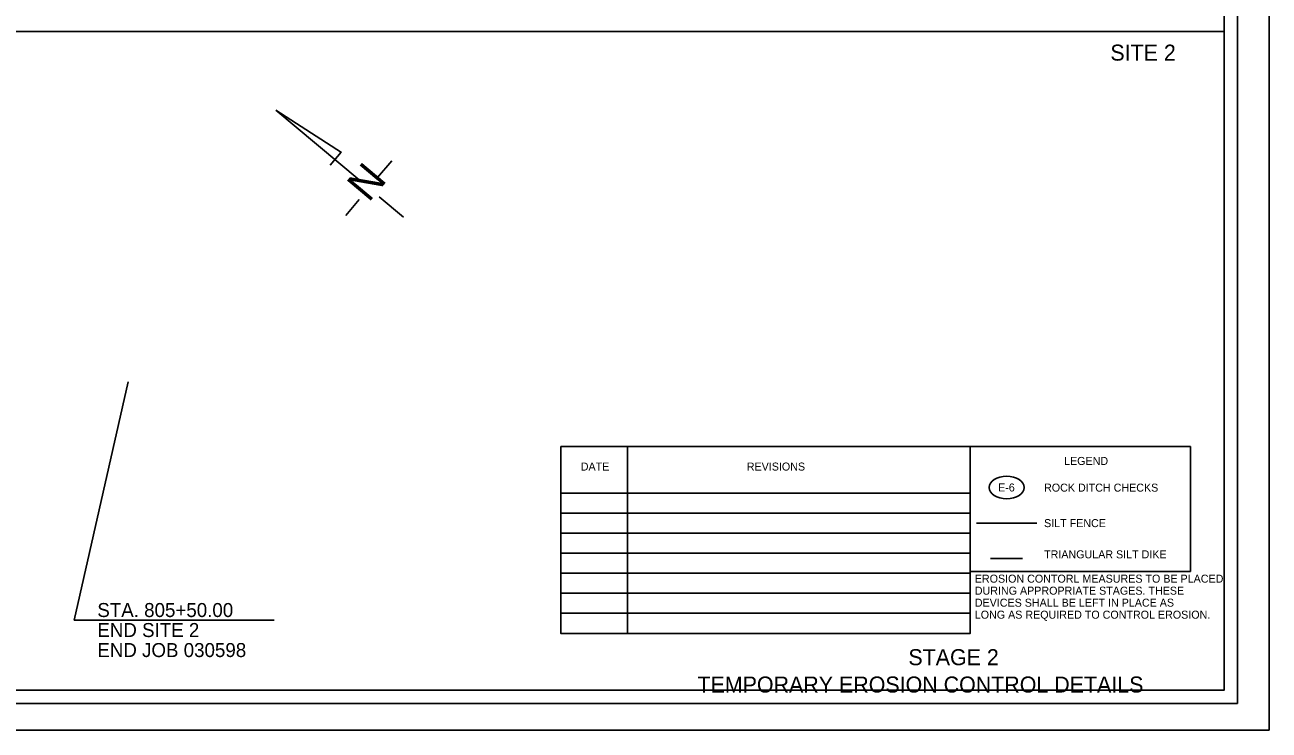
# Model space of a CAD drawing. Extents: x 814841 to 962585, y -174183 to 1802800.
# Drawn here: x 819784 to 820716, y 1801733 to 1802262 of the extents above; entities that cross this region are included whole.
import ezdxf

# ---------------------------------------------------------------- set-up
doc = ezdxf.new("R2010")
doc.units = 0
for name, color, linetype in [('_Silt Dike Legend', 7, 'Continuous'), ('Default', 7, 'Continuous'), ('Legend', 7, 'Continuous'), ('R_Border', 7, 'Continuous'), ('R_Border Notes', 7, 'Continuous'), ('R_Border Title', 7, 'Continuous'), ('R_Detour Annot', 7, 'Continuous'), ('R_Draft', 7, 'Continuous'), ('R_No Plot', 7, 'Continuous')]:
    doc.layers.add(name, color=color, linetype=linetype)

# ---------------------------------------------------------------- blocks, each defined once
blk = doc.blocks.new('E-6')
at = {"layer": 'Default'}
blk.add_ellipse((0, 0), major_axis=(13.15, 0), ratio=0.638788, dxfattribs=at)
blk.add_text('E-6', height=6, dxfattribs=at).set_placement((-6.43, -3))

msp = doc.modelspace()

# ---------------------------------------------------------------- linework, layer by layer
at = {"layer": '_Silt Dike Legend'}
msp.add_line((820507.62, 1801862.13), (820531.62, 1801862.13), dxfattribs=at)
at = {"layer": 'Legend'}
msp.add_line((820497.19, 1801888.52), (820542.22, 1801888.52), dxfattribs=at)
msp.add_lwpolyline([(820492.43, 1801945.92), (820657.43, 1801945.92), (820657.43, 1801852.39), (820492.43, 1801852.39)], close=True, dxfattribs=at)
at = {"layer": 'R_Border'}
for q in [(820692.68, 1802780.6), (819111.78, 1801753.3)]:
    msp.add_line((820692.68, 1801753.3), q, dxfattribs=at)
at = {"layer": 'R_Border Notes'}
for p, q in [((820235.41, 1801945.92), (820492.43, 1801945.92)), ((820235.41, 1801945.92), (820235.41, 1801805.92)), ((820185.41, 1801910.92), (820492.43, 1801910.92)), ((820185.41, 1801895.92), (820492.43, 1801895.92)), ((820185.41, 1801880.92), (820492.43, 1801880.92)), ((820185.41, 1801865.92), (820492.43, 1801865.92)), ((820185.41, 1801850.92), (820492.43, 1801850.92)), ((820185.41, 1801835.92), (820492.43, 1801835.92)), ((820185.41, 1801820.92), (820492.43, 1801820.92)), ((820185.41, 1801805.92), (820492.43, 1801805.92))]:
    msp.add_line(p, q, dxfattribs=at)
msp.add_lwpolyline([(820185.41, 1801945.92), (820492.43, 1801945.92), (820492.43, 1801805.92), (820185.41, 1801805.92)], close=True, dxfattribs=at)
at = {"layer": 'R_Draft'}
for p, q in [((819971.87, 1802198.16), (820021.12, 1802166.33)), ((820034.18, 1802145.86), (819971.87, 1802198.16)), ((820012.48, 1802156.71), (820020.79, 1802166.61)), ((820048.13, 1802147.56), (820058.72, 1802160.18)), ((820067.61, 1802117.8), (820049.28, 1802133.18)), ((820024.32, 1802119.2), (820034.24, 1802131.02)), ((819820.58, 1801815.89), (819861.14, 1801994.39)), ((819970.58, 1801815.89), (819820.58, 1801815.89))]:
    msp.add_line(p, q, dxfattribs=at)
at = {"layer": 'R_No Plot'}
for points in [[(819049.74, 1802800.08), (820716.44, 1802800.08), (820716.44, 1801733.39), (819049.74, 1801733.39)], [(819121.78, 1802770.6), (820369.48, 1802770.6), (820369.48, 1802721.2), (820457.18, 1802721.2), (820577.68, 1802721.2), (820577.68, 1802609.54), (820682.68, 1802609.54), (820682.68, 1801763.3), (819121.78, 1801763.3)], [(819121.78, 1802256.95), (820682.68, 1802256.95), (820682.68, 1801763.3), (819121.78, 1801763.3)], [(819121.78, 1802256.95), (820682.68, 1802256.95), (820682.68, 1801763.3), (819121.78, 1801763.3)], [(819121.78, 1802256.95), (820682.68, 1802256.95), (820682.68, 1801763.3), (819121.78, 1801763.3)], [(819121.78, 1802256.95), (820682.68, 1802256.95), (820682.68, 1801763.3), (819121.78, 1801763.3)], [(819121.78, 1802256.95), (820682.68, 1802256.95), (820682.68, 1801763.3), (819121.78, 1801763.3)], [(819121.78, 1802256.95), (820682.68, 1802256.95), (820682.68, 1801763.3), (819121.78, 1801763.3)], [(819121.78, 1802256.95), (820682.68, 1802256.95), (820682.68, 1801763.3), (819121.78, 1801763.3)]]:
    msp.add_lwpolyline(points, close=True, dxfattribs=at)

# ---------------------------------------------------------------- block references
at = {"layer": 'Legend', "rotation": -1.8065126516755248e-10}
msp.add_blockref('E-6', (820519.7, 1801915.24), dxfattribs=at)

# ---------------------------------------------------------------- texts
at = {"layer": 'Legend'}
for s, p in [('LEGEND', (820562.74, 1801932.13)), ('DATE', (820200.41, 1801927.92)), ('  REVISIONS', (820320.41, 1801927.92)), ('ROCK DITCH CHECKS', (820547.74, 1801912.13)), ('SILT FENCE', (820547.74, 1801885.52)), ('TRIANGULAR SILT DIKE', (820547.74, 1801862.13)), ('EROSION CONTORL MEASURES TO BE PLACED', (820495.8, 1801843.9)), ('DURING APPROPRIATE STAGES. THESE ', (820495.8, 1801834.9)), ('DEVICES SHALL BE LEFT IN PLACE AS ', (820495.8, 1801825.9)), ('LONG AS REQUIRED TO CONTROL EROSION.', (820495.8, 1801816.9))]:
    msp.add_text(s, height=6, dxfattribs=at).set_placement(p)
at = {"layer": 'R_Border'}
msp.add_text('SITE 2', height=12, dxfattribs=at).set_placement((820597.44, 1802235.17))
at = {"layer": 'R_Border Title'}
for s, p in [('STAGE 2', (820446.01, 1801782.05)), ('TEMPORARY EROSION CONTROL DETAILS', (820287.88, 1801761.55))]:
    msp.add_text(s, height=12, dxfattribs=at).set_placement(p)
at = {"layer": 'R_Detour Annot'}
for s, p in [('STA. 805+50.00', (819837.96, 1801818.14)), ('END SITE 2', (819837.96, 1801803.14)), ('END JOB 030598', (819837.96, 1801788.14))]:
    msp.add_text(s, height=10.5, dxfattribs=at).set_placement(p)
at = {"layer": 'R_Draft'}
msp.add_text('N', height=23.27, rotation=49.991, dxfattribs=at).set_placement((820041.34, 1802128.33))

doc.saveas('drawing.dxf')
